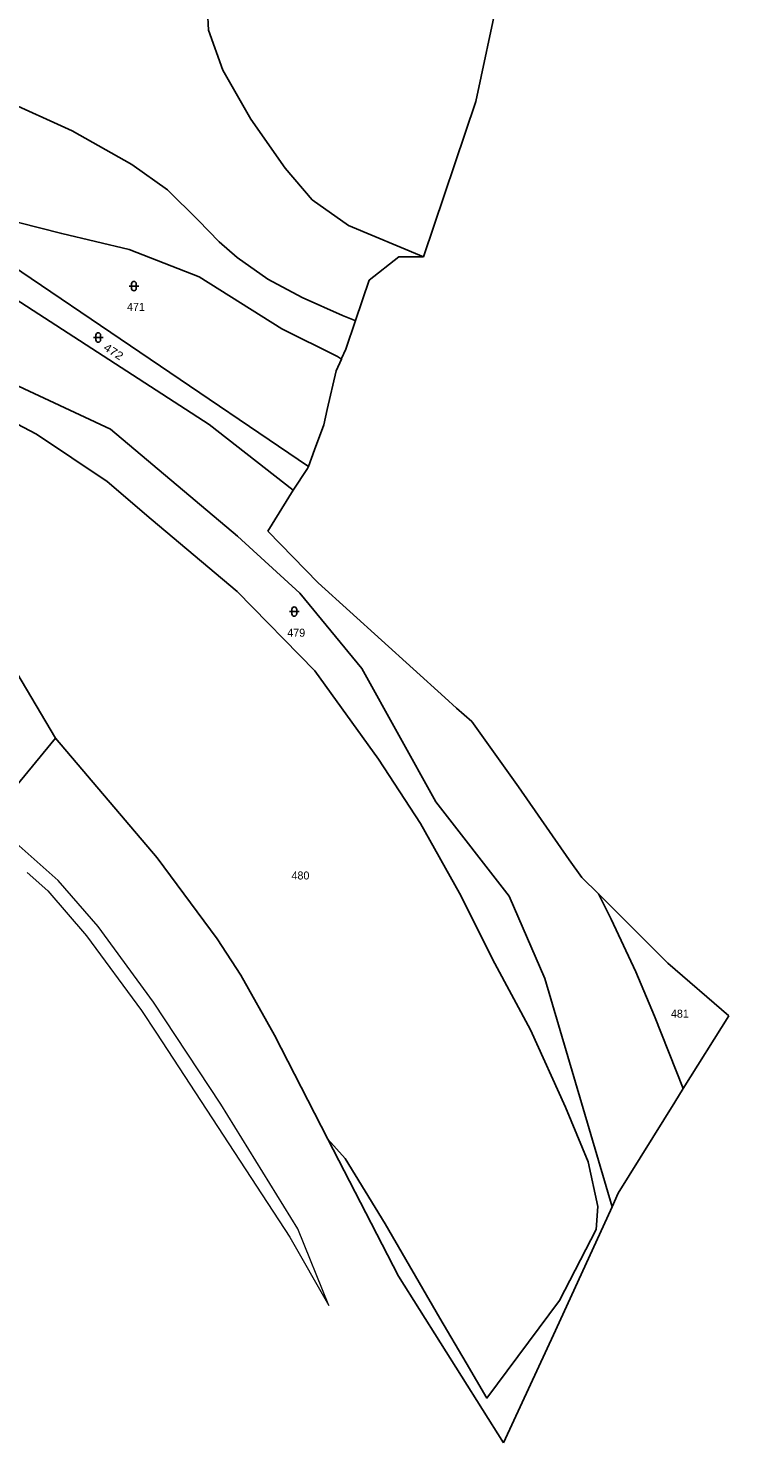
# Model space of a CAD drawing. Extents: x -769392 to -767038, y -1018329 to -1015269.
# Drawn here: x -767980.5 to -767831.9, y -1016492.7 to -1016192.3 of the extents above; entities that cross this region are included whole.
import ezdxf

# ---------------------------------------------------------------- set-up
doc = ezdxf.new("R2010")
doc.units = 0
doc.header["$LTSCALE"] = 0.68
for name, color, linetype, lineweight in [('1', 7, 'Continuous', 25), ('13', 7, 'Continuous', 13), ('3', 7, 'Continuous', 25)]:
    doc.layers.add(name, color=color, linetype=linetype, lineweight=lineweight)
doc.layers.add('2', color=7, linetype='Continuous')

msp = doc.modelspace()

# ---------------------------------------------------------------- linework, layer by layer
at = {"layer": '1'}
for p, q in [((-767876.25, -1016164.12), (-767885.56, -1016207.78)), ((-767885.56, -1016207.78), (-767896.62, -1016240.82)), ((-767901.89, -1016240.83), (-767908.16, -1016245.76)), ((-767896.62, -1016240.82), (-767901.89, -1016240.83)), ((-767908.16, -1016245.76), (-767911.07, -1016254.35)), ((-767911.07, -1016254.35), (-767913.13, -1016260.42)), ((-767915.19, -1016265.02), (-767914.06, -1016262.5)), ((-767914.06, -1016262.5), (-767914.02, -1016262.4)), ((-767914.02, -1016262.4), (-767913.13, -1016260.42)), ((-767915.19, -1016265.02), (-767917.08, -1016273.24)), ((-767917.08, -1016273.24), (-767917.81, -1016276.45)), ((-767919.78, -1016281.82), (-767917.81, -1016276.45)), ((-767921.08, -1016285.34), (-767919.78, -1016281.82)), ((-767921.24, -1016285.79), (-767924.32, -1016290.35)), ((-767921.24, -1016285.79), (-767921.08, -1016285.34)), ((-767924.32, -1016290.35), (-767929.7, -1016299.07)), ((-767929.7, -1016299.07), (-767919.03, -1016310.05)), ((-767892.14, -1016334.38), (-767919.03, -1016310.05)), ((-767889.66, -1016336.63), (-767892.14, -1016334.38)), ((-767889.66, -1016336.63), (-767886.41, -1016339.46)), ((-767886.41, -1016339.46), (-767876.49, -1016353.37)), ((-767974.79, -1016343), (-767983.92, -1016354.13)), ((-767953.18, -1016368.47), (-767974.79, -1016343)), ((-767876.49, -1016353.37), (-767865.73, -1016368.84)), ((-767940.45, -1016385.65), (-767953.18, -1016368.47)), ((-767865.73, -1016368.84), (-767863.01, -1016372.59)), ((-767863.01, -1016372.59), (-767859.49, -1016376.11)), ((-767859.49, -1016376.11), (-767844.76, -1016390.83)), ((-767935.45, -1016393.39), (-767940.45, -1016385.65)), ((-767844.76, -1016390.83), (-767831.86, -1016401.97)), ((-767928.31, -1016406.08), (-767935.45, -1016393.39)), ((-767831.86, -1016401.97), (-767841.52, -1016417.46)), ((-767916.95, -1016428.18), (-767928.31, -1016406.08)), ((-767841.52, -1016417.46), (-767843.31, -1016420.33)), ((-767843.31, -1016420.33), (-767855.29, -1016439.67)), ((-767901.97, -1016457.31), (-767916.95, -1016428.18)), ((-767855.29, -1016439.67), (-767856.61, -1016442.56)), ((-767856.61, -1016442.56), (-767868.61, -1016468.82)), ((-767879.68, -1016492.67), (-767901.97, -1016457.31)), ((-767868.61, -1016468.82), (-767879.68, -1016492.67))]:
    msp.add_line(p, q, dxfattribs=at)
for points in [[(-767896.62, -1016240.82), (-767912.56, -1016234.13), (-767920.31, -1016228.66), (-767925.99, -1016221.98), (-767933.3, -1016211.56), (-767939.27, -1016201.17), (-767942.28, -1016192.67), (-767942.7, -1016184.35), (-767943.08, -1016182.35), (-767947.41, -1016178.51), (-767951.73, -1016175.96), (-767976.13, -1016166.75), (-767982.69, -1016161.31), (-767988.39, -1016150.96), (-767989.96, -1016141.37), (-767991.47, -1016134.18), (-767994.3, -1016128.17), (-768001.87, -1016121.89), (-768005.47, -1016120.25), (-768014.65, -1016117.84), (-768027.12, -1016115.35), (-768039.52, -1016112.92), (-768071.74, -1016102.81), (-768088.91, -1016099.25)], [(-767911.07, -1016254.35), (-767911.35, -1016254.24), (-767913.83, -1016253.23), (-767922.4, -1016249.43), (-767929.72, -1016245.52), (-767936.18, -1016240.92), (-767940.03, -1016237.62), (-767944.46, -1016232.99), (-767951.01, -1016226.59), (-767958.59, -1016221.19), (-767971.23, -1016214.07), (-767985.88, -1016207.38), (-767992.63, -1016204.28), (-768002.1, -1016199.96), (-768015.26, -1016193.2), (-768022.33, -1016189.3), (-768026.9, -1016184.75), (-768028.26, -1016178.48), (-768028.24, -1016168.79)], [(-768038.45, -1016218.29), (-768028.38, -1016221.43), (-768011.42, -1016227.29), (-767996.34, -1016230.05), (-767973.42, -1016235.88), (-767959.11, -1016239.22), (-767944.29, -1016245.02), (-767926.74, -1016256.09), (-767914.88, -1016261.94), (-767914.06, -1016262.5)], [(-768008.26, -1016234.04), (-767988.38, -1016239.77), (-767921.08, -1016285.34)], [(-767924.32, -1016290.35), (-767942.13, -1016276.4), (-767983.33, -1016249.71), (-768008.26, -1016234.04)], [(-767992.35, -1016263.74), (-767963.08, -1016277.39), (-767936.1, -1016300.15), (-767922.89, -1016312.25), (-767909.74, -1016328.25), (-767894, -1016356.57), (-767878.44, -1016376.56), (-767870.9, -1016394.06), (-767856.61, -1016442.56)], [(-767974.79, -1016343), (-767987.14, -1016322.24), (-767994.73, -1016301.82), (-767996.8, -1016284.58), (-767994.86, -1016270.26)], [(-767994.86, -1016270.26), (-767992.44, -1016271.3), (-767978.79, -1016278.45), (-767963.78, -1016288.55), (-767954.49, -1016296.53), (-767936.21, -1016311.91), (-767919.7, -1016328.71), (-767906.23, -1016347.52), (-767897.29, -1016361.17), (-767889.01, -1016375.92), (-767881.48, -1016390.88), (-767873.96, -1016404.95), (-767866.53, -1016421.37), (-767861.72, -1016433.03), (-767859.65, -1016442.5), (-767859.98, -1016447.38), (-767867.78, -1016462.48), (-767883.19, -1016483.2), (-767887.56, -1016475.7), (-767893.18, -1016466.2), (-767904.81, -1016446.15), (-767913.26, -1016432.32), (-767916.95, -1016428.18)], [(-767841.52, -1016417.46), (-767847.58, -1016402.09), (-767851.57, -1016392.65), (-767856.84, -1016381.48), (-767859.49, -1016376.11)]]:
    msp.add_lwpolyline(points, dxfattribs=at)
at = {"layer": '13'}
msp.add_lwpolyline([(-767980.79, -1016371.56), (-767976.4, -1016375.46), (-767968.15, -1016384.99), (-767956.54, -1016400.84), (-767953.31, -1016405.7), (-767925.05, -1016448.99), (-767916.73, -1016463.53), (-767923.29, -1016447.27), (-767939.69, -1016420.79), (-767953.98, -1016399.08), (-767965.73, -1016383.05), (-767974.2, -1016373.27), (-767988.9, -1016360.2)], dxfattribs=at)
at = {"layer": '3'}
for p, q in [((-767959.111, -1016247.011), (-767957.109, -1016247.011)), ((-767958.611, -1016246.511), (-767958.611, -1016247.512)), ((-767957.609, -1016247.512), (-767957.609, -1016246.511)), ((-767966.681, -1016257.931), (-767964.679, -1016257.931)), ((-767966.181, -1016257.431), (-767966.181, -1016258.432)), ((-767965.179, -1016258.432), (-767965.179, -1016257.431)), ((-767925.071, -1016316.151), (-767923.069, -1016316.151)), ((-767924.571, -1016315.651), (-767924.571, -1016316.652)), ((-767923.569, -1016316.652), (-767923.569, -1016315.651))]:
    msp.add_line(p, q, dxfattribs=at)
for centre, start, end in [((-767958.11, -1016246.5109), 0, 180), ((-767958.11, -1016247.5109), 180, 359.98789), ((-767965.68, -1016257.4309), 0, 180), ((-767965.68, -1016258.4309), 180, 359.98789), ((-767924.07, -1016315.6509), 0, 180), ((-767924.07, -1016316.6509), 180, 359.98789)]:
    msp.add_arc(centre, 0.5, start, end, dxfattribs=at)

# ---------------------------------------------------------------- texts
at = {"layer": '2'}
for s, p in [('471', (-767959.58, -1016252.285)), ('479', (-767925.56, -1016321.485)), ('480', (-767924.66, -1016373.045)), ('481', (-767844.12, -1016402.395))]:
    msp.add_text(s, height=1.7, dxfattribs=at).set_placement(p)
at = {"layer": '2', "width": 1.15}
msp.add_text('472', height=1.7, rotation=327, dxfattribs=at).set_placement((-767964.731, -1016260.466))

doc.saveas('drawing.dxf')
